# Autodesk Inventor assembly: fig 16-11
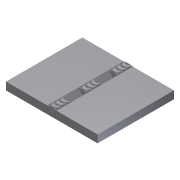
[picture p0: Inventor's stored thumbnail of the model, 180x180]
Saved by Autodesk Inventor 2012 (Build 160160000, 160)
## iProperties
Created: 2005-03
Part Number: fig 16-11
Document SubType Name: Weldment
Designer: CADCIM
Manufacturer: Standard
Standards Organization: Custom
Author: CADCIM
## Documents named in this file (2)
- C:\Users\CadCim\Documents\SAILESH\inventor-2011-fact-prt\c16-inv-2011-prt\c16_inv_2012_prt\fig 16-11\fig 16-11.iam
- C:\Users\CadCim\Documents\SAILESH\inventor-2011-fact-prt\c16-inv-2011-prt\fig-16-11\Part1.ipt
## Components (2 placed, 1 different names)
1. Part1:1 — Mate:1, Flush:1, Flush:2
2. Part1:2 — Mate:1, Flush:1, Flush:2
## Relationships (3: Flush 2, Mate 1)
- Mate:1: Part1:1 ↔ Part1:2
- Flush:1: Part1:1 ↔ Part1:2
- Flush:2: Part1:1 ↔ Part1:2
